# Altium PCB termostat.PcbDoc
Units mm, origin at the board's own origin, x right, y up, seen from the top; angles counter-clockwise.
Board outline 105.66 x 36.58 mm, 2 copper layers (Top Layer, Bottom Layer); 31 components, 29 nets, 148 pads, 60 vias.
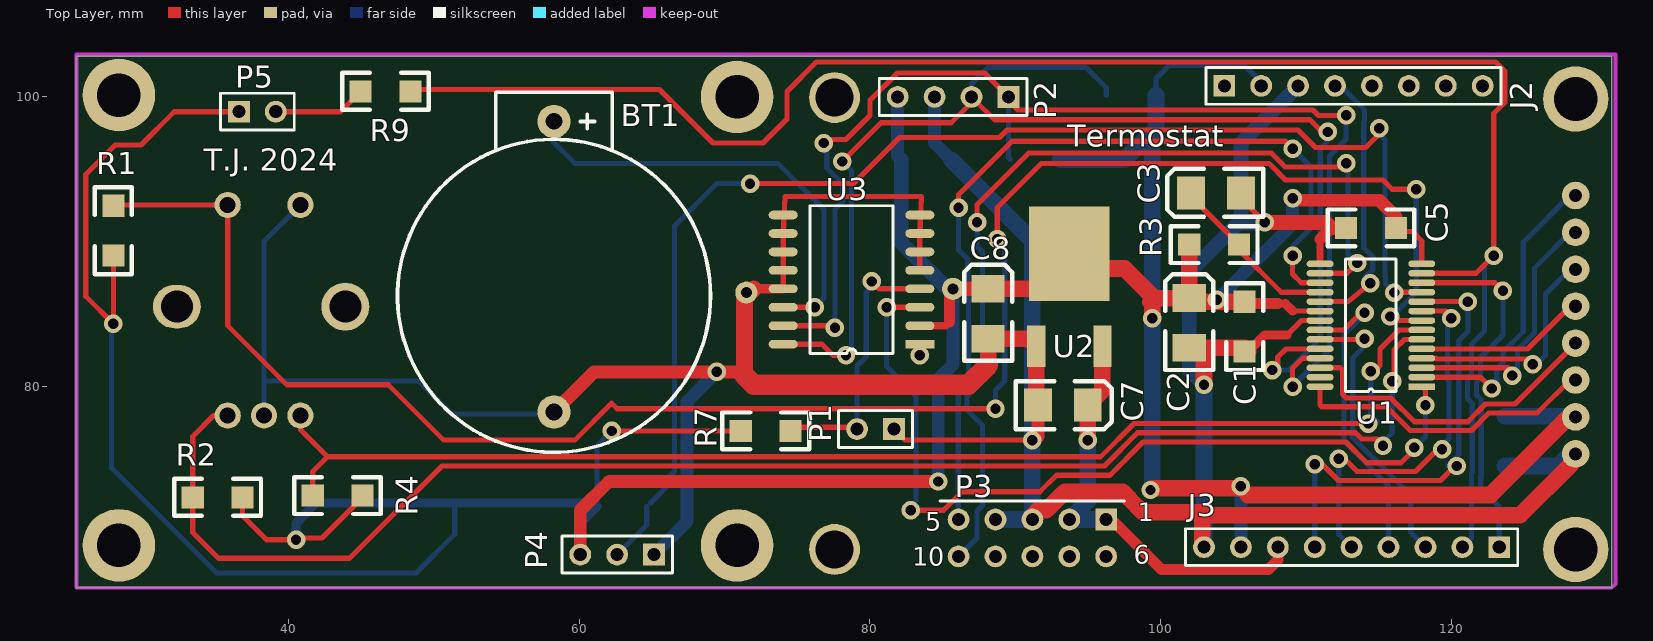
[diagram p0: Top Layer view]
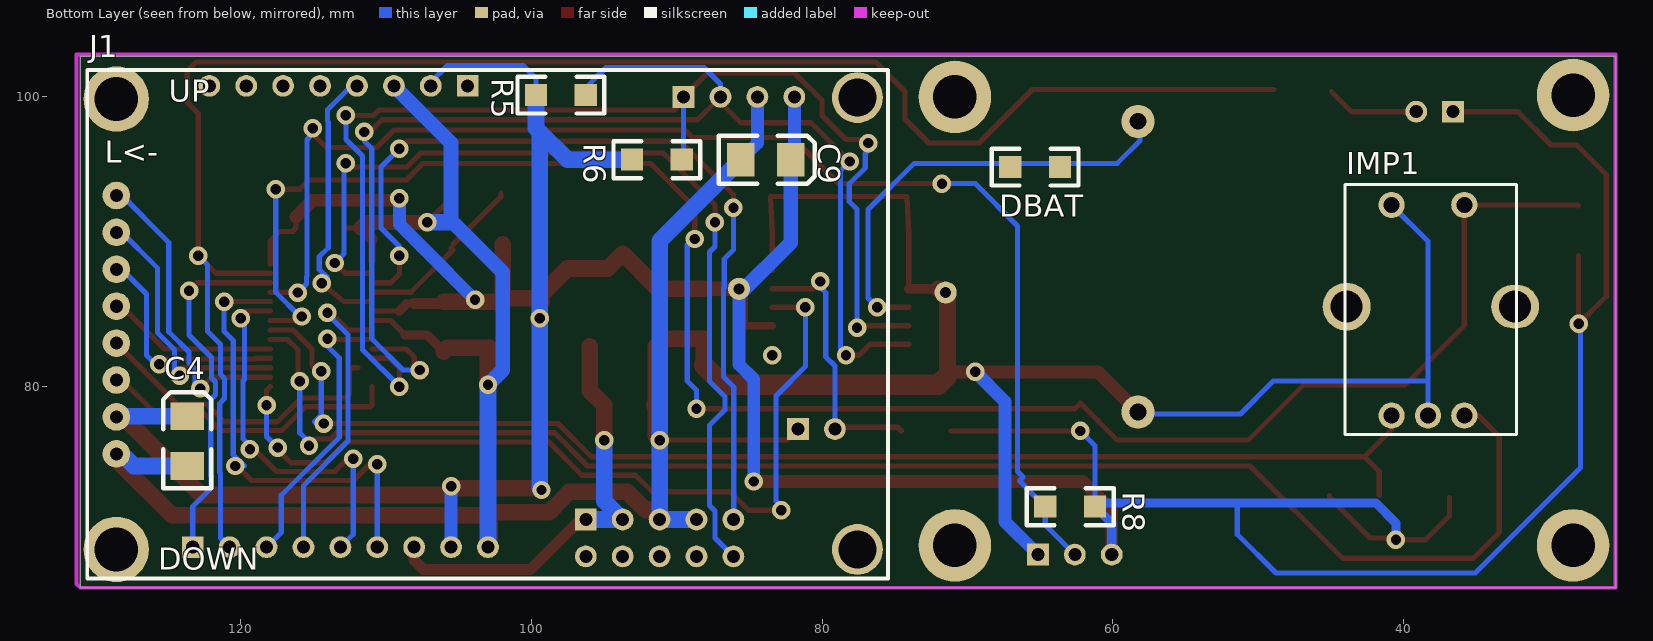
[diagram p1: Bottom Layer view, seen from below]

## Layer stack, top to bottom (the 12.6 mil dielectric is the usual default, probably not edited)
Top Solder: solder mask 0.0102, Solder Resist, Dk 3.5
Top Layer: signal copper 0.0356
Dielectric 1: dielectric 0.32, FR-4, Dk 4.8
Bottom Layer: signal copper 0.0356
Bottom Solder: solder mask 0.0102, Solder Resist, Dk 3.5

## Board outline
25.4,66.167 131.064,66.167 131.064,102.743 25.4,102.743

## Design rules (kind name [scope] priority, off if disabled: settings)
Clearance [All] p1: gap=0.254
PolygonConnect [All] p1: connectstyle=Relief reliefconductorwidth=0.254 reliefentries=4 polygonreliefangle="90 Angle" airgapwidth=0.254
RoutingVias [All] p1: holewidth=0.711 width=1.27 viastyle="Through Hole" minholewidth=0.711 minwidth=1.27 maxholewidth=0.711 maxwidth=1.27
SolderMaskExpansion [All] p1: expansion=0.102
Width [All] p1: maxlimit=0.356 minlimit=0.356 preferedwidth=0.356
30 further rules are at their usual default settings.

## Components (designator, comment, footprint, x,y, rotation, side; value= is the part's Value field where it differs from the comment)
BT1 "3VDC" BAT 57.912,86.487 r90 top
C1 "100nF" 1206 105.791,85.852 r270 top
C2 "10u" 3528 101.981,86.106 r90 top
C3 "10u" 3528 102.108,93.345 r180 top
C4 "10u" 3528 123.698,77.978 r90 bottom
C5 "Cap" 1206 112.776,90.932 r0 top
C7 "10u" 3528 94.996,78.74 r0 top
C8 "10u" 3528 88.138,86.741 r90 top
C9 "10u" 3528 82.169,95.631 r180 bottom
DBAT "" 1206 67.056,95.123 r180 bottom
IMP1 "IMP_PIHER" IMP_PIHER 38.608,85.217 r180 bottom
J1 "LCD" lcd_128_160 104.775,78.105 r0 bottom
J2 "ICSP" HDR1X8 104.394,100.711 r0 top
J3 "EXP" HDR1X9 123.317,68.961 r180 top
P1 "RES" HDR1X2 81.661,77.089 r180 top
P2 "I2C" HDR1X4 89.535,99.949 r180 top
P3 "Header 5X2A" HDR2X5_CEN 96.266,70.866 r180 top
P4 "DS18B20" HDR1X3 65.151,68.453 r180 top
P5 "LED" HDR1X2 36.576,98.933 r0 top
R1 "" 1206 27.94,89.027 r90 top
R2 "" 1206 36.83,72.39 r180 top
R3 "10k" 1206 105.41,89.789 r180 top
R4 "" 1206 45.085,72.517 r180 top
R5 "1k" 1206 96.266,100.076 r0 bottom
R6 "1k" 1206 93.091,95.631 r180 bottom
R7 "1k" 1206 71.12,76.962 r0 top
R8 "1k" 1206 61.214,71.755 r0 bottom
R9 "1k" 1206 44.958,100.33 r0 top
U1 "Atmega4808_28" "atmega4808_28 - duplicate" 117.983,80.01 r180 top
U2 "SPX1117" to252-3l 93.726,83.566 r0 top
U3 "ds3231" DS3231 83.439,82.931 r180 top

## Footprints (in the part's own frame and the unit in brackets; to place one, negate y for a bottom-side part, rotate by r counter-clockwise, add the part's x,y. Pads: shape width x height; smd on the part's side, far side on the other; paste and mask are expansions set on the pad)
1206 [mil]
  rect 60x60 smd: 1(0,0) 2(135,0)
  silkscreen extent -50,-50 185,50
3528 [mil]
  rect 75x90 smd: 1(0,0) 2(-135,0)
  silkscreen extent -195,-65 65,65
"atmega4808_28 - duplicate" [mm]
  rect 1.85x0.45 smd: 1(0,0)
  oval 1.85x0.45 smd: 2(0,-0.65) 3(0,-1.3) 4(0,-1.95) 5(0,-2.6) 6(0,-3.25) 7(0,-3.9) 8(0,-4.55) 9(0,-5.2) 10(0,-5.85) 11(0,-6.5) 12(0,-7.15) 13(0,-7.8) 14(0,-8.45) 15(7,-8.45) 16(7,-7.8) 17(7,-7.15) 18(7,-6.5) 19(7,-5.85) 20(7,-5.2) 21(7,-4.55) 22(7,-3.9) 23(7,-3.25) 24(7,-2.6) 25(7,-1.95) 26(7,-1.3) 27(7,-0.65) 28(7,0)
  silkscreen extent 1.76,-8.78 5.24,0.33
BAT [mil]
  round 90 hole 45: 1(463.58,-13.78) 2(-323.82,-13.78)
  silkscreen extent -433,-438 542,410
DS3231 [mm]
  rect 2x0.6 smd: 1(0,0)
  oval 2x0.6 smd: 2(0,-1.27) 3(0,-2.54) 4(0,-3.81) 5(0,-5.08) 6(0,-6.35) 7(0,-7.62) 8(0,-8.89) 9(9.4,-8.89) 10(9.4,-7.62) 11(9.4,-6.35) 12(9.4,-5.08) 13(9.4,-3.81) 14(9.4,-2.54) 15(9.4,-1.27) 16(9.4,0)
  silkscreen extent 1.84,-9.53 7.56,0.64
HDR1X2 [mm] "Connector; Header; 2 Position"
  rect 1.5x1.5 hole 0.9: 1(0,0)
  round 1.5 hole 0.9: 2(2.54,0)
  silkscreen extent -1.27,-1.27 3.81,1.27
HDR1X3 [mm] "Connector; Header; 3 Position"
  rect 1.5x1.5 hole 0.9: 1(0,0)
  round 1.5 hole 0.9: 2(2.54,0) 3(5.08,0)
  silkscreen extent -1.27,-1.27 6.35,1.27
HDR1X4 [mm] "Connector; Header; 4 Position"
  rect 1.5x1.5 hole 0.9: 1(0,0)
  round 1.5 hole 0.9: 2(2.54,0) 3(5.08,0) 4(7.62,0)
  silkscreen extent -1.27,-1.27 8.89,1.27
HDR1X8 [mm] "Connector; Header; 8 Position"
  rect 1.5x1.5 hole 0.9: 1(0,0)
  round 1.5 hole 0.9: 2(2.54,0) 3(5.08,0) 4(7.62,0) 5(10.16,0) 6(12.7,0) 7(15.24,0) 8(17.78,0)
  silkscreen extent -1.27,-1.27 19.05,1.27
HDR1X9 [mm] "Connector; Header; 9 Position"
  rect 1.5x1.5 hole 0.9: 1(0,0)
  round 1.5 hole 0.9: 2(2.54,0) 3(5.08,0) 4(7.62,0) 5(10.16,0) 6(12.7,0) 7(15.24,0) 8(17.78,0) 9(20.32,0)
  silkscreen extent -1.27,-1.27 21.59,1.27
HDR2X5_CEN [mm] "Connector; Header; 5x2 Position"
  rect 1.5x1.5 hole 0.9: 1(0,0)
  round 1.5 hole 0.9: 2(2.54,0) 3(5.08,0) 4(7.62,0) 5(10.16,0) 6(0,2.54) 7(2.54,2.54) 8(5.08,2.54) 9(7.62,2.54) 10(10.16,2.54)
  silkscreen extent -1.27,-1.27 11.43,-1.27
IMP_PIHER [mm]
  round 1.8 hole 1.1: 1(-2.2,-7.2) 2(0.3,-7.2) 3(2.8,-7.2) 4(-2.2,7.3) 5(2.8,7.3)
  round 3.3 hole 2.2: 71(-5.3,0.3)
  oval 3.3x3 hole 2.2: 72(6.3,0.3)
  silkscreen extent -5.4,-8.5 6.4,8.7
lcd_128_160 [mm]
  round 3.5 hole 2.6: 0(-27.2,-21.8) 0(-27.2,9.3)
  round 4.5 hole 3: 0(23.8,-21.7) 0(23.8,9.3)
  round 1.9 hole 0.9: 1(23.8,2.72) 2(23.8,0.18) 3(23.8,-2.36) 4(23.8,-4.9) 5(23.8,-7.44) 6(23.8,-9.98) 7(23.8,-12.52) 8(23.8,-15.06)
  silkscreen extent -29.3,-23.7 25.8,11.3
to252-3l [mm]
  rect 1.25x2.85 smd: 1(-2.275,-0.775) 3(2.275,-0.775)
  rect 5.55x6.5 smd: 2(0,5.6)

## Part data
BT1: library part Battery, "Multicell Battery"
C1: library part Cap, "Capacitor"
C2 C3 C4 C7 C8 C9: library part ELECTRO2, "Electrolytic Capacitor"
C5: "Capacitor"
J1 J2: library part "Header 8", "Header, 8-Pin"
J3: library part "Header 9", "Header, 9-Pin"
P1 P5: library part "Header 2", "Header, 2-Pin"
P2: library part "Header 4", "Header, 4-Pin"
P3: "Header, 5-Pin, Dual row"
P4: library part "Header 3", "Header, 3-Pin"
R1 R2 R3 R4 R5 R6 R7 R8 R9: library part Res2, "Resistor"

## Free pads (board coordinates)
  round 5 hole 3: 0(70.866,99.949) 1(70.866,69.088) 2(28.321,69.088) 3(28.321,100.076)
  round 1.524 hole 0.762: 0(71.501,86.487) 1(85.725,86.741)

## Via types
v1: diameter 1.27, hole 0.711, Top Layer to Bottom Layer, 60 vias

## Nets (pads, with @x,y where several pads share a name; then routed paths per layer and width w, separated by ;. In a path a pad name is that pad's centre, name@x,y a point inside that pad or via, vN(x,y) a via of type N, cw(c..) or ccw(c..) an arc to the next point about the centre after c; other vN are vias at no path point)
+3,3VD: C1.1 C2.1 C4.1 C5.2 C8.1 C9.1 J1.2 J2.2 J3.8 P2.4 P4.3 P5.1 pad.1@85.725,86.741 R1.1 R2.1 R3.2 R4.1 R5.2 R6.1 R7.1 R8.1 U1.14 U1.20 U2.2 U3.2 | length 319.6
  Top Layer w0.356: R1.1 v1(27.94,84.328) 26.035,86.233 26.035,94.615 28.067,96.647 29.845,96.647 32.131,98.933 P5.1 ; R2.1 36.83,71.12 38.481,69.469 v1(40.513,69.469) ; v1@40.132,69.596 42.291,69.596 45.085,72.39 R4.1 ; v1(62.23,76.962) R7.1 ; 85.217,84.201 85.471,84.455 ; pad.1@85.471,86.106 pad.1@85.725,86.36 ; v1(99.314,72.898) v1@99.441,73.025 ; v1@105.537,73.025 v1(105.537,73.152) ; C1.1@106.045,85.852 C1.1@106.172,85.725 ; 109.1,85.21 U1.20 ; 116.205,91.694 C5.2 116.459,90.678 117.348,90.678 117.983,90.043 U1.14 ; J1.2@128.217,78.052 J1.2@128.321,78.052
  Top Layer w0.508: U3.2 85.217,84.201
  Top Layer w0.635: 108.585,85.725 109.1,85.21
  Top Layer w0.762: 85.471,84.455 pad.1@85.471,86.106 ; pad.1@85.725,86.36 pad.1@86.106,86.741 ; C1.1@106.172,85.725 108.077,85.725
  Top Layer w0.889: P4.3 60.071,71.501 62.052,73.482 v1(84.709,73.482) ; v1@109.093,92.837 115.062,92.837 116.205,91.694
  Top Layer w1.016: pad.1@86.106,86.741 C8.1
  Top Layer w1.143: C8.1 91.301,86.741 U2.2 94.754,88.138 97.536,88.138 99.568,86.106 ; v1@99.441,73.025 v1@105.537,73.025 ; v1(99.441,84.709) 99.441,85.725 99.314,85.852 99.568,86.106 ; R3.2 C2.1 ; 106.007,72.555 122.72,72.555 J1.2@128.217,78.052 ; C1.1@106.045,85.852 102.235,85.852 C2.1 ; 99.568,86.106 C2.1
  Bottom Layer w0.356: v1(27.94,84.328) 27.813,84.455 27.813,74.422 35.052,67.183 48.768,67.183 51.435,69.85 51.435,72.009 ; R8.1 61.214,75.946 v1(62.23,76.962) ; C9.1@81.915,95.885 C9.1 ; 99.441,97.536 99.695,97.79 ; R5.2 99.695,101.219 100.584,102.108 105.791,102.108 106.934,100.965 J2.2
  Bottom Layer w0.635: v1(40.513,69.469) 40.513,70.612 41.91,72.009 51.435,72.009 60.96,72.009 R8.1 60.071,70.612 P4.3
  Bottom Layer w0.889: C9.1@81.915,95.885 P2.4 ; v1(84.709,73.482) 84.709,80.518 85.725,81.534 pad.1@85.725,86.36 ; v1(103.886,85.979) 107.442,89.535 ; J3.8 v1(105.537,73.152) ; 107.569,89.662 109.093,91.186 v1(109.093,92.964)
  Bottom Layer w1.016: C9.1 82.169,89.916 pad.1@85.725,86.36
  Bottom Layer w1.143: R6.1 97.536,95.631 99.441,97.536 v1(99.441,84.709) 99.441,73.025 v1(99.314,72.898) ; 99.695,97.79 R5.2 ; C4.1 128.247,77.978 J1.2@128.321,78.052
+5VD: C7.1 J3.7 P3.1 P3.2 U2.3 | length 29.8
  Top Layer w0.356: P3.1 P3.1@96.647,70.866
  Top Layer w0.762: P3.1@96.647,70.866 100.076,67.437 107.442,67.437 108.077,68.072 J3.7
  Top Layer w1.143: v1(94.996,76.327) C7.1 96.001,79.745 U2.3
  Bottom Layer w1.143: v1(94.996,76.327) 94.996,72.136 P3.2 P3.1
D_GND: BT1.2 C1.2 C2.2 C3.2 C4.2 C5.1 C7.2 C8.2 C9.2 IMP1.2 IMP1.4 J1.1 J2.3 J3.9 P1.1 P2.3 P3.3 P3.4 P4.1 pad.0@71.501,86.487 U1.15 U1.21 U2.1 U3.5 U3.6 U3.7 U3.8 U3.9 U3.10 U3.11 U3.12 U3.13 | length 276.4
  Top Layer w0.356: U3.13 U3.12 U3.11 U3.10 74.166,93.091 83.566,93.091 U3.7 U3.6 U3.5 ; P1.1 82.423,76.327 v1(91.186,76.327) 91.313,76.327 v1@91.567,76.581 ; C2.2@102.87,82.677 C2.2@102.997,82.55 ; C3.2 105.537,92.964 v1(107.188,91.313) ; 108.712,83.566 109.706,84.56 U1.21 ; 111.76,90.932 C5.1 ; J1.1@128.321,74.727 J1.1@128.321,75.512
  Top Layer w0.508: U1.15@110.983,88.646 110.983,90.155
  Top Layer w0.635: pad.0@72.009,86.741 U3.13 ; C1.2@106.045,82.423 107.188,83.566 108.712,83.566
  Top Layer w0.762: 110.983,90.155 111.76,90.932
  Top Layer w0.889: BT1.2@58.135,78.135 61.026,81.026 v1(69.469,81.026) 71.12,81.026 ; v1@91.567,76.581 C7.2
  Top Layer w1.016: v1(107.188,91.313) 111.379,91.313 111.76,90.932
  Top Layer w1.143: 71.374,80.772 71.374,86.106 pad.0@72.009,86.741 ; 88.138,81.493 C8.2 90.93,83.312 U2.1 91.451,78.856 C7.2 ; P3.3@91.186,71.12 91.585,71.519 92.15,71.519 93.403,72.771 97.409,72.771 97.853,72.326 97.853,72.293 98.773,71.374 102.87,71.374 ; C2.2@102.87,82.677 105.791,82.677 C1.2@106.045,82.423 ; J3.9 102.87,69.088 102.87,71.374 ; v1(102.997,80.137) C2.2@102.997,82.55 ; J1.1@128.321,74.727 124.752,71.158 103.086,71.158 102.87,71.374
  Top Layer w1.397: 71.374,80.772 72.009,80.137 86.782,80.137 88.138,81.493
  Bottom Layer w0.356: IMP1.2 38.308,90.017 IMP1.4 IMP1.4@40.869,92.456 ; 38.354,80.391 48.955,80.391 51.211,78.135 BT1.2@58.135,78.135 ; J1.1@128.321,74.727 J1.1@128.321,75.512
  Bottom Layer w0.889: P4.1 67.424,70.726 67.424,78.981 v1(69.469,81.026) ; P2.3 84.455,96.774 C9.2
  Bottom Layer w1.016: v1(102.997,80.137) 101.981,81.153 101.981,87.884 105.537,91.44 105.537,96.774 J2.3
  Bottom Layer w1.143: C9.2 91.186,90.043 v1(91.186,76.327) ; P3.4 P3.3 v1@91.186,76.073 ; J3.9 v1(102.997,80.137) ; 105.537,91.313 v1(107.188,91.313) ; C4.2 127.358,74.549 J1.1@128.321,75.512
DS18B20: P4.2 R8.2 U1.11 | length 90.8
  Top Layer w0.356: v1(71.755,93.98) 78.867,93.98 82.042,97.155 88.927,97.155 89.435,97.663 109.474,97.663 110.668,96.469 114.122,96.469 115.443,97.79 v1(115.062,97.79) ; v1(116.078,86.487) 116.101,86.51 U1.11
  Bottom Layer w0.356: P4.2 64.643,70.485 R8.2 ; R8.2@64.897,72.009 66.421,73.533 66.167,73.787 66.548,74.168 66.548,91.059 69.469,93.98 v1(71.755,93.98) ; v1(115.062,97.79) 115.062,97.409 115.443,97.028 115.443,87.615 115.494,87.564 115.494,87.071 v1(116.078,86.487)
I2C_SCL: P2.1 R6.2 U1.25 U3.15 | length 84.9
  Top Layer w0.356: U3.15 v1@77.597,84.201 ; v1(76.835,96.774) 77.089,97.028 78.359,97.028 80.01,98.679 80.01,99.715 81.895,101.6 87.884,101.6 P2.1 ; P2.1@89.535,99.695 90.173,99.057 110.493,99.057 110.871,98.679 v1(112.776,98.679) ; v1(109.093,80.01) 109.093,81.28 109.773,81.96 U1.25
  Bottom Layer w0.356: v1(76.835,96.774) 76.581,96.52 77.038,96.063 77.038,95.062 78.13,93.97 78.13,92.751 77.597,92.217 v1(77.597,84.074) ; P2.1 89.535,95.758 R6.2 ; v1(109.093,80.01) 111.633,82.55 111.633,95.885 112.776,97.028 v1(112.776,98.679)
I2C_SDA: P2.2 R5.1 U1.24 U3.16 | length 89.6
  Top Layer w0.356: U3.16 76.708,82.931 77.47,82.169 v1(78.359,82.169) ; v1(78.105,95.504) 80.772,98.171 85.598,98.171 87.185,99.758 88.57,98.374 110.287,98.374 111.506,97.155 v1(111.506,97.536) ; v1(107.696,81.153) 108.077,81.534 108.077,82.042 108.645,82.61 U1.24
  Bottom Layer w0.356: v1(78.105,95.504) 78.74,94.869 78.74,82.55 v1(78.359,82.169) ; P2.2 86.995,100.838 88.138,101.981 94.869,101.981 96.266,100.584 R5.1 ; v1(107.696,81.153) 108.839,81.153 110.998,83.312 110.998,96.393 111.506,96.901 v1(111.506,97.536)
IMP_A: IMP1.3 R2.2 U1.6 | length 105.1
  Top Layer w0.356: IMP1.3 34.837,78.017 33.401,76.581 R2.2 33.401,69.977 35.179,68.199 44.196,68.199 50.546,74.549 96.139,74.549 98.425,76.835 113.426,76.835 113.858,76.403 v1@114.93,76.403 ; v1(115.316,75.946) v1@115.316,76.2 ; v1@116.078,80.264 116.078,82.55 116.788,83.26 U1.6
  Bottom Layer w0.356: v1(115.316,75.946) 115.316,76.2 115.951,76.835 v1(115.951,80.391)
IMP_B: IMP1.1 R4.2 U1.7 | length 89
  Top Layer w0.356: IMP1.1 40.808,77.048 42.672,75.184 ; R4.2 41.656,74.168 42.672,75.184 ; v1(114.3,77.47) 98.171,77.47 95.885,75.184 42.672,75.184 ; v1(114.478,81.073) 114.728,81.073 115.113,81.458 115.113,82.601 116.422,83.91 U1.7
  Bottom Layer w0.356: v1(114.3,77.47) 114.808,77.47 114.935,77.597 114.478,78.054 v1(114.478,81.073)
IMP_SW: IMP1.5 R1.2 U1.8 | length 130.6
  Top Layer w0.356: R1.2 28.001,92.517 IMP1.5 35.808,84.207 39.878,80.137 46.863,80.137 50.673,76.327 59.69,76.327 62.23,78.867 62.611,78.486 v1(88.646,78.486) ; v1(88.773,90.17) 88.773,92.329 91.821,95.377 107.469,95.377 108.612,94.234 115.316,94.234 115.951,93.599 v1(117.602,93.599) ; v1(115.824,84.836) 116.1,84.56 U1.8
  Bottom Layer w0.356: v1(88.646,78.486) 88.646,79.756 89.281,80.391 89.281,89.789 88.9,90.17 v1(88.773,90.17) ; v1(115.824,84.836) 115.936,84.836 117.602,86.502 v1(117.602,93.599)
LCD_BLK: J1.8 U1.2 | length 21.1
  Top Layer w0.356: U1.2 122.032,80.66 v1(122.809,79.883) v1@122.936,80.01
  Bottom Layer w0.356: v1(122.809,79.883) 123.198,80.272 123.139,80.33 123.139,81.214 123.571,81.646 123.571,82.396 124.968,83.793 124.968,89.939 J1.8@128.321,93.292
LCD_CS: J1.7 U1.3 | length 18.4
  Top Layer w0.356: U1.3 119.252,81.31 ; 119.253,81.309 123.923,81.309 124.333,80.899 v1(124.206,80.772)
  Bottom Layer w0.356: v1(124.206,80.772) 124.561,81.127 124.561,82.524 125.73,83.693 125.73,88.161 J1.7@128.321,90.752
LCD_DC: J1.6 U1.4 | length 15.7
  Top Layer w0.356: U1.4 118.958,81.96 118.999,81.919 125.252,81.919 v1(125.628,81.543)
  Bottom Layer w0.356: v1(125.628,81.543) 125.866,81.543 126.492,82.169 126.492,86.383 J1.6@128.321,88.212
LCD_MOSI: J1.4 U1.26 | length 21.4
  Top Layer w0.356: 111.962,81.31 112.365,81.31 112.522,81.153 112.522,79.502 112.786,79.238 115.834,79.238 117.475,77.597 121.148,77.597 122.367,78.816 124.409,78.816 128.321,82.728 J1.4@128.321,83.132
LCD_RST: J1.5 U1.5 | length 11.6
  Top Layer w0.356: U1.5 125.259,82.61 J1.5@128.321,85.672
LCD_SCK: J1.3 U1.28 | length 20.8
  Top Layer w0.356: U1.28@110.983,80.003 110.983,78.74 111.095,78.628 115.555,78.628 117.196,76.987 121.4,76.987 122.62,78.207 125.936,78.207 J1.3@128.321,80.592
NetP1_2: P1.2 R7.2 U3.4 | length 18.6
  Top Layer w0.356: R7.2 74.803,77.216 P1.2@79.121,77.216 ; v1(80.137,87.249) 80.645,86.741 U3.4
  Bottom Layer w0.356: P1.2@79.121,77.216 79.121,81.422 79.756,82.057 79.756,86.487 80.137,86.868 v1(80.137,87.249)
NetP5_2: P5.2 R9.1 | length 6.4
  Top Layer w0.356: P5.2 43.561,98.933 R9.1
P2: J3.1 U1.12 | length 24.9
  Top Layer w0.356: U1.12 123.025,87.16 v1(123.571,86.614)
  Bottom Layer w0.356: J3.1 123.317,71.755 122.047,73.025 122.047,73.829 122.072,73.855 122.072,79.111 121.742,79.441 121.742,80.325 122.022,80.604 122.022,82.017 123.571,83.566 v1(123.571,86.614)
P3: J3.2 R9.2 U1.13 | length 119.7
  Top Layer w0.356: R9.2@48.895,100.457 65.532,100.457 69.215,96.774 72.644,96.774 74.295,98.425 74.295,100.33 76.327,102.362 123.063,102.362 123.698,101.727 123.698,99.568 122.936,98.806 v1(122.936,89.027) 121.719,87.81 U1.13
  Bottom Layer w0.356: J3.2 121.412,69.596 121.412,74.056 121.463,74.107 121.463,78.858 121.133,79.189 121.133,80.577 121.412,80.857 121.412,82.931 122.301,83.82 122.301,88.392 v1(122.936,89.027)
P4: J3.3 U1.23 | length 19.7
  Top Layer w0.356: U1.23 113.994,83.26 v1(114.046,83.312)
  Bottom Layer w0.356: v1@114.3,83.058 113.233,81.991 113.233,76.52 117.221,72.532 117.221,69.977 J3.3
P5: J3.4 U1.22 | length 22
  Top Layer w0.356: U1.22 112.612,83.91 113.792,85.09 v1@114.3,85.09
  Bottom Layer w0.356: v1@114.3,85.09 114.138,85.09 112.624,83.576 112.624,76.268 115.697,73.194 J3.4
  other v1: 114.046,85.09
P6: J3.5 U1.9 | length 26.5
  Top Layer w0.356: v1(112.268,75.057) 112.649,75.057 113.538,74.168 117.551,74.168 119.075,75.692 v1(119.38,75.692) ; U1.9 119.641,85.21 120.015,84.836 v1(120.015,84.709)
  Bottom Layer w0.356: v1(112.268,75.057) 112.268,69.85 J3.5 ; v1(119.38,75.692) 119.456,75.768 v1@119.456,75.997 ; v1@119.634,75.819 119.444,76.01 119.863,76.429 119.863,80.39 119.761,80.491 119.761,84.455 v1(120.015,84.709)
P7: J3.6 U1.10 | length 32.3
  Top Layer w0.356: v1(110.617,74.676) 111.125,74.676 112.243,73.558 119.263,73.558 120.254,74.549 v1(120.396,74.549) ; U1.10 121.277,85.86 121.269,85.852 v1(121.158,85.852)
  Bottom Layer w0.356: J3.6 v1(110.617,74.676) ; v1(120.396,74.549) 119.761,74.549 120.523,75.311 120.523,83.185 121.158,83.82 v1(121.158,85.852)
RTC_TOO: U1.1 U3.3 | length 59.2
  Top Layer w0.356: v1(81.153,85.471) U3.3 ; v1(82.804,71.501) 85.07,71.501 86.34,72.771 91.694,72.771 92.837,73.914 96.52,73.914 98.806,76.2 112.776,76.2 114.198,74.778 116.561,74.778 117.475,75.692 v1(117.475,75.819) ; U1.1 118.237,79.756 v1@118.237,79.121
  Bottom Layer w0.356: v1(81.153,85.471) 81.153,81.407 83.185,79.375 83.185,72.136 82.804,71.755 v1(82.804,71.501) ; v1(117.475,75.819) 118.237,76.581 v1(118.237,78.74)
STER1: P3.5 U1.17 | length 59.3
  Top Layer w0.356: v1(86.106,92.329) 86.106,93.218 89.789,96.901 108.585,96.901 v1@108.966,96.52 ; v1(109.093,89.027) 109.093,87.757 109.69,87.16 U1.17@110.729,87.16
  Bottom Layer w0.356: P3.5 86.081,70.891 86.081,79.985 86.792,80.696 86.792,86.802 86.741,86.853 86.741,87.986 86.741,88.798 86.106,89.433 86.106,90.17 ; 86.106,90.297 v1@86.106,92.278 ; v1@109.093,88.773 109.093,89.662 110.363,90.932 110.363,95.123 v1(109.093,96.393) v1@109.22,96.52
STER2: P3.10 U1.16 | length 63.9
  Top Layer w0.356: v1(87.376,91.313) 87.376,92.532 90.932,96.088 107.62,96.088 108.585,95.123 112.522,95.123 v1(112.776,95.377) ; U1.16 112.829,87.81 v1(113.538,88.519)
  Bottom Layer w0.356: P3.10 87.376,69.596 87.376,71.444 87.757,71.825 87.757,77.358 86.69,78.425 86.69,79.309 87.757,80.376 87.757,89.281 87.376,89.662 v1(87.376,91.313) ; v1(112.776,95.377) 113.284,95.377 112.903,94.996 112.903,89.154 v1(113.538,88.519)
UC_RESET: C3.1 R3.1 U1.18 | length 11.9
  Top Layer w0.356: C3.1 102.108,93.091 R3.1 ; R3.1@105.537,89.535 105.41,89.408 108.308,86.51 U1.18
UPDI: J2.4 U1.19 | length 19.6
  Top Layer w0.356: U1.19 112.911,85.86 v1(114.427,87.122) v1@114.427,86.741
  Bottom Layer w0.356: J2.4 112.395,100.711 114.046,99.06 114.046,98.283 113.995,98.232 113.995,89.57 114.605,88.961 114.605,88.077 114.046,87.518 114.046,87.503 v1(114.427,87.122)
VBAT: BT1.1 U3.14 | length 31
  Top Layer w0.356: U3.14 v1(76.2,85.471)
  Bottom Layer w0.356: BT1.1@58.135,98.135 58.135,96.932 59.69,95.377 73.66,95.377 76.835,92.202 76.835,86.106 v1(76.2,85.471)
pads on no net: DBAT.1 DBAT.2 IMP1.71 IMP1.72 J1.0 J2.1 J2.5 J2.6 J2.7 J2.8 P3.6 P3.7 P3.8 P3.9 U1.27 U3.1
copper on no net:
  other v1: 83.439,82.169

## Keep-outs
Keep-Out Layer:
  lines w0.254: 25.4,102.743 25.4,66.167 131.064,66.167 131.318,66.421 131.318,102.87 ; 25.4,102.87 131.191,102.87

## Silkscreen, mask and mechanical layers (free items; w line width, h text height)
Top Overlay:
  text "Termostat" at 93.599,96.52 h1.52
  text "T.J. 2024" at 34.163,94.869 h1.52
